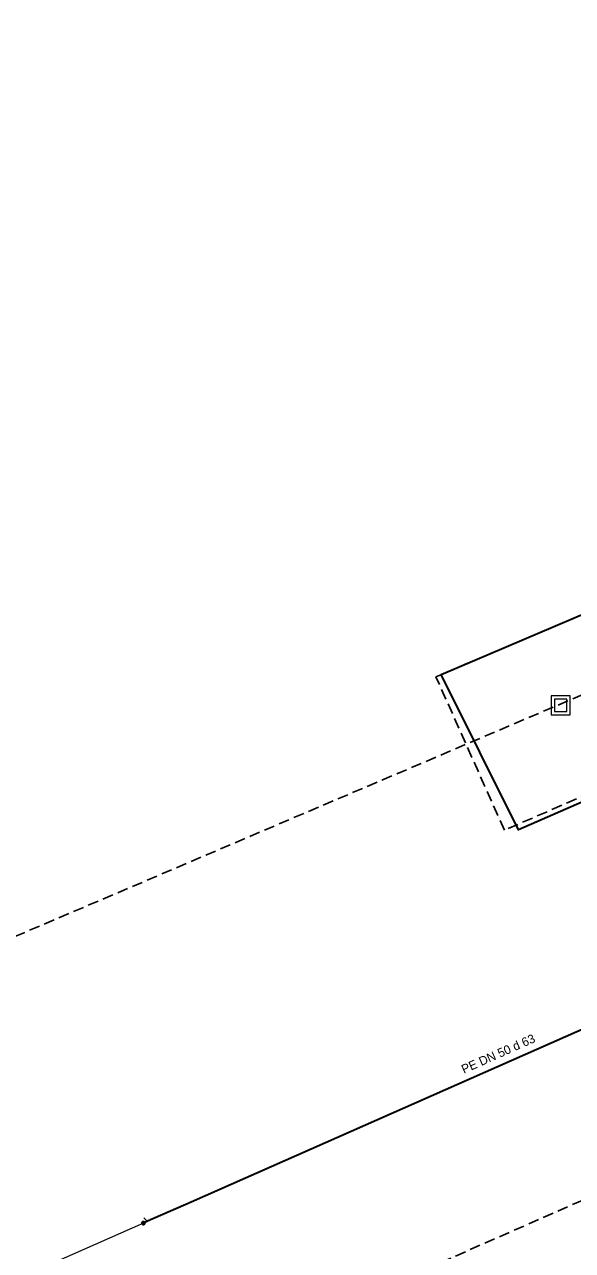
# Model space of a CAD drawing. Extents: x -772868 to -772180, y -1034353 to -1034014.
# Drawn here: x -772518.9 to -772444.7, y -1034180.3 to -1034014.3 of the extents above; entities that cross this region are included whole.
import ezdxf

# ---------------------------------------------------------------- set-up
doc = ezdxf.new("R2010")
doc.units = 0
doc.header["$LTSCALE"] = 0.48
doc.linetypes.add('MEDIUM_DASHED', pattern=[4.5, 3, -1.5])
for name, color, linetype, lineweight in [('15', 7, 'Continuous', 13), ('16', 7, 'Continuous', 35), ('18', 7, 'Continuous', 13), ('24', 7, 'MEDIUM_DASHED', 25), ('27', 7, 'Continuous', 35), ('59', 7, 'Continuous', 13), ('62', 7, 'MEDIUM_DASHED', 25)]:
    doc.layers.add(name, color=color, linetype=linetype, lineweight=lineweight)
doc.layers.add('17', color=7, linetype='Continuous')

msp = doc.modelspace()

# ---------------------------------------------------------------- linework, layer by layer
at = {"layer": '15'}
for points in [[(-772502.576, -1034176.621), (-772502.583, -1034176.569), (-772502.6, -1034176.519), (-772502.629, -1034176.475), (-772502.666, -1034176.438), (-772502.711, -1034176.411), (-772502.761, -1034176.394), (-772502.814, -1034176.39), (-772502.865, -1034176.397), (-772502.914, -1034176.416), (-772502.958, -1034176.445), (-772502.994, -1034176.484), (-772503.02, -1034176.529), (-772503.036, -1034176.58), (-772503.039, -1034176.632), (-772503.031, -1034176.684), (-772503.011, -1034176.733), (-772502.98, -1034176.776), (-772502.941, -1034176.81), (-772502.895, -1034176.836), (-772502.843, -1034176.85), (-772502.791, -1034176.852), (-772502.74, -1034176.842), (-772502.691, -1034176.821), (-772502.649, -1034176.79), (-772502.615, -1034176.749), (-772502.591, -1034176.703), (-772502.578, -1034176.652)], [(-772502.607, -1034176.621), (-772502.613, -1034176.572), (-772502.63, -1034176.526), (-772502.657, -1034176.486), (-772502.695, -1034176.454), (-772502.739, -1034176.432), (-772502.787, -1034176.421), (-772502.836, -1034176.421), (-772502.882, -1034176.434), (-772502.926, -1034176.458), (-772502.962, -1034176.491), (-772502.989, -1034176.532), (-772503.005, -1034176.579), (-772503.009, -1034176.628), (-772503.002, -1034176.676), (-772502.983, -1034176.721), (-772502.953, -1034176.761), (-772502.914, -1034176.792), (-772502.87, -1034176.812), (-772502.823, -1034176.822), (-772502.774, -1034176.82), (-772502.727, -1034176.805), (-772502.684, -1034176.78), (-772502.649, -1034176.746), (-772502.624, -1034176.704), (-772502.61, -1034176.657)], [(-772502.637, -1034176.621), (-772502.642, -1034176.576), (-772502.659, -1034176.534), (-772502.688, -1034176.499), (-772502.723, -1034176.472), (-772502.766, -1034176.455), (-772502.811, -1034176.45), (-772502.855, -1034176.456), (-772502.897, -1034176.475), (-772502.931, -1034176.503), (-772502.958, -1034176.54), (-772502.975, -1034176.582), (-772502.978, -1034176.627), (-772502.972, -1034176.672), (-772502.953, -1034176.713), (-772502.924, -1034176.747), (-772502.887, -1034176.773), (-772502.843, -1034176.789), (-772502.799, -1034176.792), (-772502.754, -1034176.784), (-772502.713, -1034176.764), (-772502.679, -1034176.735), (-772502.654, -1034176.697), (-772502.64, -1034176.654)], [(-772502.667, -1034176.621), (-772502.671, -1034176.58), (-772502.69, -1034176.543), (-772502.717, -1034176.512), (-772502.752, -1034176.491), (-772502.792, -1034176.48), (-772502.833, -1034176.482), (-772502.872, -1034176.495), (-772502.906, -1034176.519), (-772502.931, -1034176.551), (-772502.946, -1034176.589), (-772502.948, -1034176.63), (-772502.941, -1034176.67), (-772502.921, -1034176.706), (-772502.892, -1034176.735), (-772502.855, -1034176.754), (-772502.815, -1034176.762), (-772502.774, -1034176.758), (-772502.735, -1034176.743), (-772502.703, -1034176.717), (-772502.681, -1034176.683), (-772502.668, -1034176.644)], [(-772502.696, -1034176.621), (-772502.701, -1034176.585), (-772502.72, -1034176.553), (-772502.745, -1034176.528), (-772502.779, -1034176.513), (-772502.816, -1034176.51), (-772502.85, -1034176.518), (-772502.882, -1034176.538), (-772502.904, -1034176.566), (-772502.918, -1034176.6), (-772502.918, -1034176.637), (-772502.907, -1034176.672), (-772502.886, -1034176.701), (-772502.855, -1034176.722), (-772502.821, -1034176.732), (-772502.784, -1034176.73), (-772502.75, -1034176.716), (-772502.723, -1034176.693), (-772502.703, -1034176.661), (-772502.696, -1034176.626)], [(-772502.727, -1034176.621), (-772502.732, -1034176.59), (-772502.749, -1034176.564), (-772502.774, -1034176.547), (-772502.804, -1034176.54), (-772502.836, -1034176.544), (-772502.863, -1034176.561), (-772502.88, -1034176.585), (-772502.889, -1034176.616), (-772502.885, -1034176.646), (-772502.87, -1034176.674), (-772502.845, -1034176.693), (-772502.816, -1034176.702), (-772502.784, -1034176.699), (-772502.757, -1034176.685), (-772502.737, -1034176.661), (-772502.727, -1034176.632)], [(-772502.757, -1034176.621), (-772502.762, -1034176.597), (-772502.779, -1034176.579), (-772502.801, -1034176.57), (-772502.826, -1034176.573), (-772502.847, -1034176.587), (-772502.858, -1034176.609), (-772502.858, -1034176.634), (-772502.845, -1034176.655), (-772502.826, -1034176.669), (-772502.801, -1034176.672), (-772502.777, -1034176.663), (-772502.762, -1034176.645)], [(-772502.787, -1034176.621), (-772502.792, -1034176.606), (-772502.806, -1034176.6), (-772502.821, -1034176.604), (-772502.828, -1034176.618), (-772502.825, -1034176.633), (-772502.811, -1034176.642), (-772502.796, -1034176.639), (-772502.787, -1034176.627)]]:
    msp.add_lwpolyline(points, close=True, dxfattribs=at)
at = {"layer": '16'}
msp.add_lwpolyline([(-772430.489, -1034121.366), (-772420.568, -1034140.293), (-772496.333, -1034173.76), (-772502.234, -1034176.368), (-772502.808, -1034176.621)], dxfattribs=at)
at = {"layer": '18'}
for points in [[(-772447.642, -1034107.795), (-772445.047, -1034107.795), (-772445.047, -1034105.199), (-772447.642, -1034105.199)], [(-772447.174, -1034107.325), (-772445.517, -1034107.325), (-772445.517, -1034105.668), (-772447.174, -1034105.668)]]:
    msp.add_lwpolyline(points, close=True, dxfattribs=at)
at = {"layer": '24'}
msp.add_lwpolyline([(-772437.845, -1034091.821), (-772428.372, -1034112.296), (-772453.961, -1034123.413), (-772463.22, -1034102.645)], close=True, dxfattribs=at)
at = {"layer": '27'}
msp.add_lwpolyline([(-772436.144, -1034091.096), (-772432.682, -1034098.491), (-772426.3, -1034112.12), (-772430.254, -1034113.846), (-772432.345, -1034114.758), (-772433.061, -1034115.071), (-772433.576, -1034115.296), (-772452.042, -1034123.356), (-772462.516, -1034102.344)], close=True, dxfattribs=at)
at = {"layer": '59'}
msp.add_line((-772502.26, -1034176.379), (-772502.73, -1034175.885), dxfattribs=at)
msp.add_lwpolyline([(-772502.808, -1034176.621), (-772536.248, -1034191.403), (-772593.274, -1034216.812), (-772609.661, -1034218.584), (-772628.148, -1034217.801), (-772643.317, -1034219.07), (-772665.82, -1034228.054), (-772692.21, -1034240.173), (-772717.474, -1034250.871), (-772752.833, -1034265.915), (-772781.509, -1034276.864), (-772761.232, -1034317.521)], dxfattribs=at)
at = {"layer": '62'}
msp.add_lwpolyline([(-772867.887, -1034286.131), (-772867.882, -1034286.117), (-772230.643, -1034014.315), (-772215.439, -1034016.495), (-772184.418, -1034059.589), (-772836.208, -1034346.326)], close=True, dxfattribs=at)

# ---------------------------------------------------------------- texts
at = {"layer": '17'}
msp.add_text('PE DN 50 d 63 ', height=1.2, rotation=24, dxfattribs=at).set_placement((-772459.442, -1034156.403))

doc.saveas('drawing.dxf')
